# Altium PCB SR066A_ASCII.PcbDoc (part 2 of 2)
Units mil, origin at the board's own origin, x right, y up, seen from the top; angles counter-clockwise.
Board outline 2000 x 2000 mil, 4 copper layers (Top Layer, Signal Layer 1, Signal Layer 2, Bottom Layer), stack 60.434 mil thick; 64 components, 14 nets, 91 pads, 124 vias.
Unrouted connection lines stored in the file: 2.
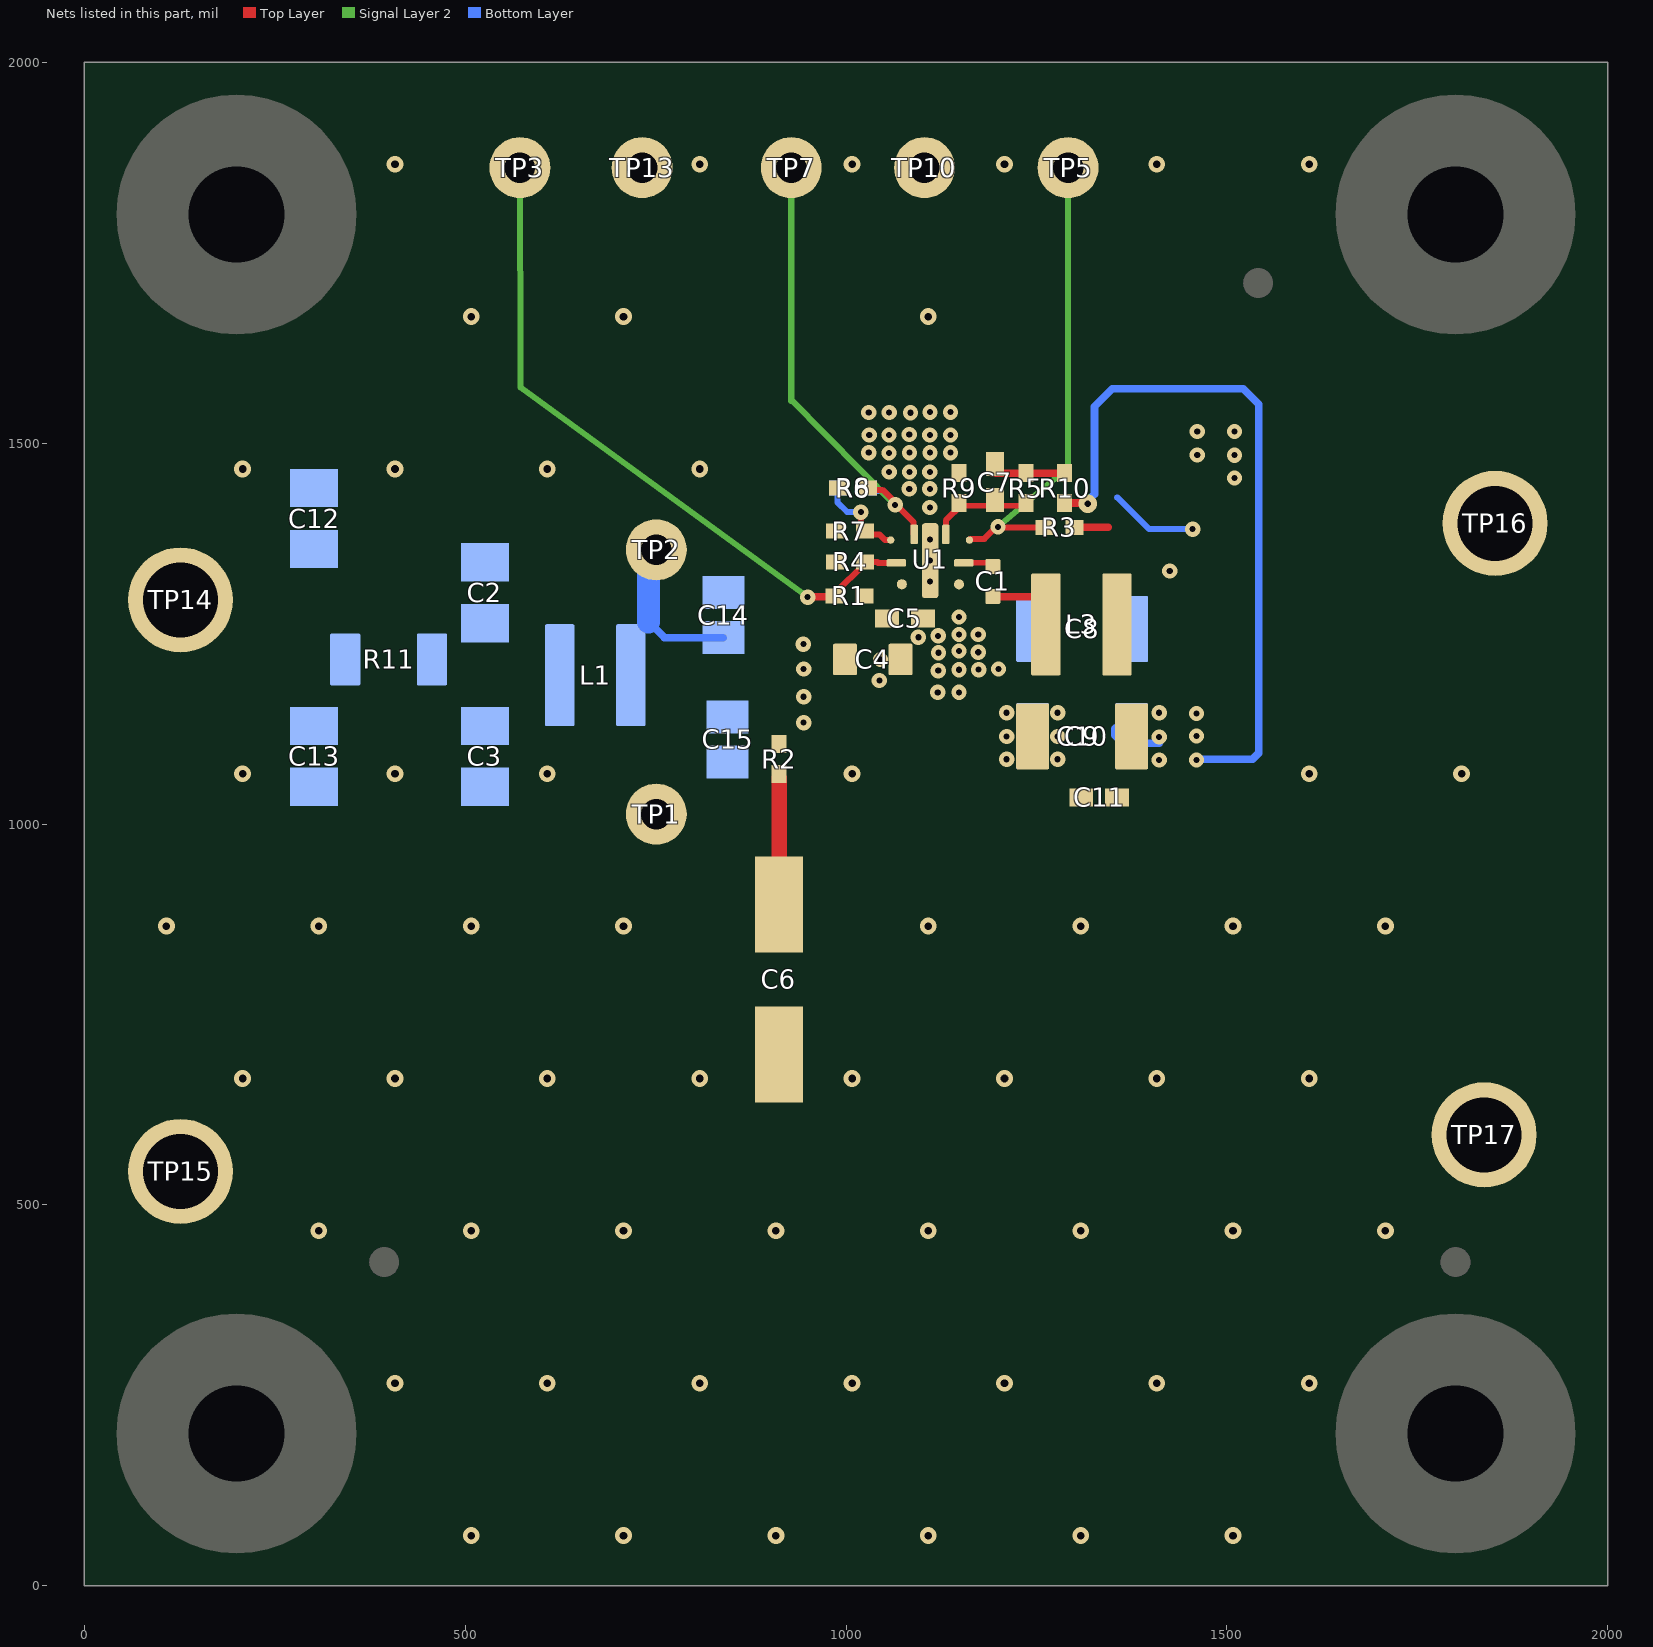
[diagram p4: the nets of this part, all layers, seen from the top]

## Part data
C1: library part CMP-0050130-1, "0.1 µF ±10% 25V Ceramic Capacitor X7R 0402 (1005 Metric)"
C2 C3 C12 C13 C14 C15: library part CMP-0007977-2, "CAP, CERM, 2.2 uF, 50 V, +/- 10%, X7R, AEC-Q200 Grade 1, 0805"
C4: library part CMP-0088943-1, "4.7µF ±10% 50V Ceramic Capacitor X7R 0805 (2012 Metric)"
C5 C11: library part CMP-0006356-2, "CAP, CERM, 0.1 uF, 50 V, +/- 10%, X7R, AEC-Q200 Grade 1, 0402"
C6: library part CMP-0011204-2, "CAP, AL, 47 uF, 50 V, +/- 20%, 0.68 ohm, AEC-Q200 Grade 2, SMD"
C7: library part CMP-0860831-1, "CAP, CERM, 22 pF, 50 V,+/- 5%, C0G/NP0, AEC-Q200 Grade 1, 0402"
C8 C9 C10: library part CMP-0043794-1, "Cap Ceramic 22uF 16V X7R 20% Pad SMD 1210 +125°C Automotive T/R"
FID1 FID2 FID3 FID4 FID5 FID6: library part CMP-0077181-1, "Fiducial mark.  There is nothing to buy or mount."
H1 H2 H3 H4: library part CMP-0003617-1, "Machine Screw, Round, #4-40 x 1/4, Nylon, Philips panhead"
H5 H6 H7 H8: library part CMP-0003610-1, "Standoff, Hex, 0.5\"L #4-40 Nylon"
L1: library part CMP-0061079-2, "Inductor, Shielded, Composite, 2.2 uH, 5.5 A, 0.0362 ohm, AEC-Q200 Grade 1, SMD"
L3: library part CMP-0120190-1, "5.6 µH Shielded Molded Inductor 5.5 A 34.7mOhm Max 1616 (4040 Metric)"
LBL1: library part CMP-0003625-1, "Thermal Transfer Printable Labels, 0.650\" W x 0.200\" H - 10,000 per roll"
Logo1: library part CMP-0074844-2
Logo2: library part CMP-0074838-1, "Texas Instrument Corporate Signature"
Logo3: library part CMP-0074847-1, "FCC_disclaimer"
Logo4: library part CMP-0074769-4
Logo5: library part CMP-0074837-2, "IEC 61010-1 Hot Surface Warning"
R1: library part CMP-0026284-2, "RES, 30.1 k, 1%, 0.063 W, AEC-Q200 Grade 0, 0402"
R2 R5 R6 R8 R10: library part CMP-0027004-2, "RES, 0, 5%, 0.063 W, 0402"
R3: library part CMP-0026823-3, "RES, 100 k, 5%, 0.063 W, AEC-Q200 Grade 0, 0402"
R4: library part CMP-0077731-1, "RES, 10.0 k, 1%, 0.063 W, AEC-Q200 Grade 0, 0402"
R7: library part CMP-0026027-3, "RES, 15.0 k, 1%, 0.063 W, AEC-Q200 Grade 0, 0402"
R9: library part CMP-0077124-1, "RES, 10.0 k, 0.1%, 0.1 W, AEC-Q200 Grade 0, 0402"
R11: library part CMP-0122408-1, "0 Ohms Jumper 0.5W, 1/2W Chip Resistor 1206 (3216 Metric) - Metal Element"
TP1 TP10 TP13: library part CMP-0055138-2, "Test Point, Miniature, Black, TH"
TP2 TP3: library part CMP-0055137-2, "Test Point, Miniature, Red, TH"
TP5: library part CMP-0055139-2, "Test Point, Miniature, White, TH"
TP7: library part CMP-0055141-2, "Test Point, Miniature, Yellow, TH"
TP14 TP15 TP16 TP17: library part CMP-0055113-1, "Terminal, Turret, TH, Double"
U1: library part CMP-0123705-1
ZZ1: library part CMP-0003616-3
ZZ2: library part CMP-0077236-1
ZZ3: library part CMP-0077237-1
ZZ4: library part CMP-0077238-1

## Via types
v1: diameter 20, hole 8, Top Layer to Bottom Layer, tented both sides, 64 vias
v2: diameter 22, hole 10, Top Layer to Bottom Layer, tented both sides, 56 vias
v3: diameter 19.68, hole 7.87, Top Layer to Bottom Layer, tented both sides, 3 vias
v4: diameter 24, hole 8, Top Layer to Bottom Layer, tented both sides, 1 vias

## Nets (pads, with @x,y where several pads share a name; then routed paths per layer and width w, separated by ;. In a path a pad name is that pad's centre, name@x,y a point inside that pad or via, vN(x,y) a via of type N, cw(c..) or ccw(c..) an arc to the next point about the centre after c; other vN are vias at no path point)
BOOT: C1.1 U1.4 | length 32.4
  Top Layer w8: U1.4@1154.69,1342.66 C1.1@1185.67,1342.97 ; C1.1@1196.63,1342.66 C1.1@1197.61,1341.67
EN: R1.1 R4.2 TP3.1 U1.9 | length 911.4
  Top Layer w8: R1.1@984.77,1299.29 986.74,1299.29 992.58,1305.13 992.58,1309.79 1017.42,1334.63 1017.42,1338.05 1023.26,1343.89 R4.2@1025.23,1343.89 1040.98,1343.89 1042.21,1342.66 U1.9@1066.11,1342.66
  Top Layer w10: v1(949.69,1297.7) 950.48,1298.49 983.98,1298.49 R1.1@984.77,1299.29
  Signal Layer 2 w8: TP3.1@572,1878 573,1574 ; 573,1573 v1(949.69,1297.7)
FB: C7.2 R5.1 R9.2 U1.6 | length 128.1
  Top Layer w8: U1.6@1131.07,1380.06 U1.6@1131.07,1380.06 1131.14,1398.49 R9.2@1151.15,1418.18 ; R9.2@1150.72,1417.98 R5.1@1232.3,1417.44
GND: C2.2 C3.2 C4.1 C5.2 C6.2 C8.1 C9.1 C10.1 C11.2 C12.2 C13.2 C14.2 C15.2 R4.1 R7.1 R8.1 R9.1 TP1.1 TP10.1 TP13.1 TP15.1 TP17.1 U1.2
  other v1: 1210.9,1084.95 1277.77,1084.95 1210.9,1114.83 1277.77,1114.95 1210.9,1145.95 1277.77,1145.95 1120.45,1172.84 1148.42,1172.84 1043.78,1188.25 1121.13,1201.21 1148.42,1202.47 1174.16,1202.61 1200.03,1203.5 1045.37,1215.97 1121.53,1224.74 1173.56,1225.42 1148.42,1227.05 1094.94,1245.07 1121,1247 1148.42,1248.79 1173.56,1248.79 1148.42,1271.54 1110.07,1415.44 1083.05,1439.87 1110.07,1439.87 1056.69,1462.14 1083.45,1462.1 1110.07,1462.1 1029.91,1487.35 1056.34,1486.97 1083.29,1487.35 1110.4,1487.35 1137,1487.35 1030.47,1510.6 1056.51,1510.6 1083.05,1511.1 1110.07,1510.6 1137,1510.6 1029.91,1540 1056.69,1540 1084.65,1539.71 1110.39,1540.49 1137,1540.49
  other v2: 508,66 708,66 908,66 1108,66 1308,66 1508,66 408,266 608,266 808,266 1008,266 1208,266 1408,266 1608,266 308,466 508,466 708,466 908,466 1108,466 1308,466 1508,466 1708,466 208,666 408,666 608,666 808,666 1008,666 1208,666 1408,666 1608,666 108,866 308,866 508,866 708,866 1108,866 1308,866 1508,866 1708,866 208,1066 408,1066 608,1066 1008,1066 1608,1066 1808,1066 208,1466 408,1466 608,1466 808,1466 508,1666 708,1666 1108,1666 408,1866 808,1866 1008,1866 1208,1866 1408,1866 1608,1866
  other v3: 1110.4,1318.05 1110.4,1345.61 1110.4,1373.17
MODE/SYNC: R6.2 R8.2 TP7.1 U1.7 | length 661.6
  Top Layer w8: R8.2@1028.95,1441.12 1031.52,1438.55 1048.07,1438.55 1064.57,1422.05 v1(1064.57,1418.93) 1065.91,1418.93 1088.81,1396.03 1088.81,1380.98 U1.7@1089.73,1380.06
  Signal Layer 2 w8: 928.13,1555.17 TP7.1@928.13,1880 ; 928.13,1557 1064.14,1418.93 v1(1064.57,1418.93)
  Bottom Layer w8: R6.2@1028.95,1440.92 1032.48,1437.39 1048.04,1437.39 1064.57,1420.86 v1(1064.57,1418.93)
NetC2_1: C2.1 C3.1 L1.1 R11.2
NetC6_1: C6.1 R2.1 | length 158.2
  Top Layer w20: R2.1@912.28,1060.32 912.44,1060.16 912.44,902.36 C6.1@912.57,902.23
NetC7_1: C7.1 R5.2 R10.1 | length 95
  Top Layer w10: C7.1@1191.91,1460.61 R5.2@1236,1460.61 R10.1@1286.9,1460.61
NetC12_1: C12.1 C13.1 R11.1 TP14.1
PGOOD: R3.2 TP5.1 U1.5 | length 613.7
  Top Layer w8: U1.5@1162.07,1372.68 1163.72,1374.33 1181.61,1374.33 1197.28,1390 v1(1199.44,1390) ; v1@1200.03,1389.41 R3.2@1259.94,1389.41
  Signal Layer 2 w8: v1@1199.45,1390.01 1291.44,1468.04 TP5.1@1291.44,1855.83
  Bottom Layer w8: v1(1199.44,1390) v1@1200.03,1389.41
RT: R6.1 R7.2 U1.8 | length 113.1
  Top Layer w8: v1@1019.46,1405.29 1019.46,1379.57 R7.2@1019.84,1379.19 ; R7.2@1029.91,1380.37 1030.47,1379.8 1044.06,1379.8 1051.02,1372.84 1058.57,1372.84 U1.8@1058.73,1372.68
  Bottom Layer w8: R6.1@989.58,1440.92 988.64,1439.99 988.64,1422.25 1001.32,1409.58 v1@1019.17,1409.58
  other v1: 1019.46,1409.29
SW: C1.2 L3.1 U1.3 | length 87.2
  Top Layer w10: C1.2@1192.85,1298.37 1253.55,1298.37 1267.84,1284.08 L3.1@1267.84,1277.76
VIN: C4.2 C5.1 C14.1 C15.1 L1.2 R1.2 R2.2 TP2.1 U1.1 | length 195.3
  Bottom Layer w10: 741,1265.3 761.83,1244.47 C14.1@839,1244.47
  Bottom Layer w30: 741,1265.3 TP2.1@741,1354
  other v1: 944.44,1133 944.44,1167 944.44,1203.5 944,1236
VOUT: C8.2 C9.2 C10.2 C11.1 L3.2 R3.1 R10.2 TP16.1 | length 1179.2
  Top Layer w10: R10.2@1286.9,1421.24 1317.29,1421.24 v4(1317.29,1420.34) ; R3.1@1299.68,1389.41 1344.05,1389.41
  Bottom Layer w8: 1356.02,1428.68 1397.76,1386.95 v1(1455,1386.95)
  Bottom Layer w10: v4(1317.29,1420.34) 1317.29,1424.13 1326.12,1432.96 1326.12,1547.71 1349.53,1571.12 1521.56,1571.12 1541.69,1551 1541.69,1093.18 1533.55,1085.04 1461.04,1085.04 v1(1460,1084) ; C10.2@1358.44,1130.53 1352.59,1124.67 1352.59,1116.39 1363.02,1105.95 v1@1411,1105.95
  other v1: 1411,1084.15 1411,1114.15 1460,1115.41 1460,1145 1411,1145.95 1424.86,1332.03 1510,1454.07 1461,1484.22 1510,1484.07 1461,1515.22 1510,1515.07
pads on no net: FID1.1 FID2.1 FID3.1 FID4.1 FID5.1 FID6.1 H1.1 H2.1 H3.1 H4.1 H5.0 H6.0 H7.0 H8.0 LBL1.0

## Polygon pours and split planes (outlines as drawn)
VIN on Top Layer "TOP_LAYER_VIN_P214" (solid, remove dead copper, pour order 214): 1081.39,1322.37 1081.39,1298.28 1069.06,1285.96 1069.06,1246.06 1040.75,1246.06 1019.46,1224.76 1019.46,1184.1 986.6,1151.25 986.6,1090.06 901.19,1090.06 901.19,1222.11 1001.46,1322.37
VOUT on Top Layer "TOP_LAYER_VOUT_P225" (solid, remove dead copper, pour order 225): 1368.86,1000.5 1458.89,1000.5 ccw(c1458.89,1038.18) 1496.57,1038.18 1496.57,1106.4 cw(c1552.17,1106.4) 1552.17,1162 1913.7,1162 ccw(c1913.7,1191.3) 1943,1191.3 1943,1521.39 ccw(c1914.4,1521.4) 1914.4,1550 1371.71,1550 ccw(c1371.71,1516.29) 1338,1516.29 1338,1031.36 ccw(c1368.86,1031.36)
GND on Top Layer "TOP_LAYER_GND_P230" (solid, remove dead copper, pour order 230): 0,2001 2,1999 2,2 2000,2 2002,4 1997,9 1997,2003
SW on Top Layer "TOP_LAYER_SW_P213" (solid, remove dead copper, pour order 213): 1138.54,1321.69 1138.85,1322 1166.75,1322 1170.42,1318.33 1215.05,1318.89 1227.23,1331.06 1292.34,1331.06 1292.34,1318.33 1292.34,1213.8 1292.34,1193.13 1235.81,1193.13 1235.81,1213.8 1159.4,1290.21 1143.55,1290.21 1138.22,1295.61
GND on Bottom Layer "BOTTOM_LAYER_GND_P233" (solid, remove dead copper, pour order 233): 4,1999 4,-2 10,4 2000,4 2000,2006 2000,1997
NetC12_1 on Bottom Layer "BOTTOM_LAYER_NETC12_1_P220" (solid, remove dead copper, pour order 220): 23.57,1100.43 23.57,1390 372.18,1390 cw(c372.18,1368.26) 393.92,1368.26 393.92,1123.39 cw(c370.95,1123.39) 370.95,1100.43
VOUT on Bottom Layer "BOTTOM_LAYER_VOUT_P221" (solid, remove dead copper, pour order 221): 1376.68,1000.5 1493.02,1000.5 ccw(c1493.02,1031.48) 1524,1031.48 1524,1535.74 ccw(c1503.74,1535.74) 1503.74,1556 1365.6,1556 ccw(c1365.6,1537.07) 1346.67,1537.11 1345.59,1031.65 ccw(c1376.68,1031.59)
VIN on Bottom Layer "BOTTOM_LAYER_VIN_P222" (solid, remove dead copper, pour order 222): 735,1119 690.44,1119 cw(c690.44,1138.44) 671,1138.44 671,1252.97 cw(c689.57,1252.97) 689.57,1271.54 943.45,1271.54 cw(c943.45,1254) 961,1253.99 961,1135.34 cw(c944.66,1135.34) 944.66,1119
NetC2_1 on Bottom Layer "BOTTOM_LAYER_NETC2_1_P224" (solid, remove dead copper, pour order 224): 431.88,1100.43 625.27,1100.43 ccw(c625.27,1123.69) 648.53,1123.69 648.53,1279.08 ccw(c633.49,1279.08) 633.49,1294.12 428.56,1294.12 ccw(c428.56,1281.32) 415.75,1281.33 415.58,1116.74 ccw(c431.88,1116.72)
GND on Signal Layer 2 "SIGNAL_LAYER_2_GND_P232" (solid, remove dead copper, pour order 232): 0,2003 4,1999 4,-2 2006,-2 2000,4 2000,1997
VOUT on Signal Layer 2 "SIGNAL_LAYER_2_VOUT_P218" (solid, remove dead copper, pour order 218): 1335.5,1021.18 1335.5,1525.92 cw(c1361.58,1525.92) 1361.58,1552 1460.5,1552 1458.5,1550 1913.84,1550 cw(c1913.84,1520.46) 1943.39,1520.45 1943.39,1199.79 cw(c1905.49,1199.78) 1905.49,1161.89 1569.07,1161.89 ccw(c1569.06,1091.82) 1499,1091.82 1499,1024.89 cw(c1470.23,1024.89) 1469.91,996.12 1359.1,997.32 cw(c1359.36,1021.18)
GND on Signal Layer 1 "SIGNAL_LAYER_1_GND_P231" (solid, remove dead copper, pour order 231): 0,2001 0,2 2,0 4,2 2002,2 2002,1988 1995,1995

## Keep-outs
Keep-Out Layer:
  the board outline again, w10
  text ".Layer_Name" at 577,-858.49 h60

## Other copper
Top Layer:
  text ".Layer_Name" at 577,-858.49 h60
Signal Layer 1:
  text ".Layer_Name" at 581,-861 h60
Signal Layer 2:
  text ".Layer_Name" at 581,-860 h60
Bottom Layer:
  text ".Layer_Name" at 577,-858.49 h60

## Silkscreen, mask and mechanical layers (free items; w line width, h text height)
Top Overlay:
  lines w3.94: 963.54,1011.75 1403.85,1011.75 1403.85,1497.83 963.54,1497.83 963.54,1011.75
  text "GND" at 673.96,1761 h35
  text "EN" at 519.44,1759 h35
  text "MODE" at 845,1759 h35
  text "GND" at 1054.07,1759 h35
  text "PGOOD" at 1207,1759 h35
  text "SYNC" at 845,1701 h35
  text "CAUTION:" at 410,1259.13 h30
  text "VOUT+" at 1755.57,1235.41 h40
  text "HOT SURFACE" at 410,1199 h30
  text "VIN_EMI+" at 44.21,1133 h40
  text "11.2mm x 12.3mm" at 968.44,962 h30
  text "GND" at 695,901 h35
  text "VOUT-" at 1756,707 h40
  text "VIN_EMI-" at 45,662 h40
  text "'.PRJ_Number'.PCB_Rev" at 731.96,286.88 h100
  text "LMR60410QEVM" at 629.63,134.15 h80
  text ".Layer_Name" at 577,-858.49 h60
Bottom Overlay:
  text ".Layer_Name" at 577,-858.49 h60
Top Paste:
  text ".Layer_Name" at 577,-858.49 h60
Bottom Paste:
  text ".Layer_Name" at 577,-858.49 h60
Top Solder:
  text ".Layer_Name" at 577,-858.49 h60
  text ".Layer_Name" at 577,-858.49 h60
Bottom Solder:
  text ".Layer_Name" at 577,-858.49 h60
Drill Guide:
  text ".Layer_Name" at 577,-858.49 h60
M1 Board Outline:
  the board outline again, w10
  text ".Layer_Name" at 577,-858.49 h60
M2 Board Dimensions:
  rectangle: 125,-400 500,-275
  rectangle: 0,-275 125,-150
  lines w7: 0,-275 1000,-275 ; 125,-400 125,-150 ; 250,-400 250,-150 ; 500,-400 500,-150 ; 750,-400 750,-150 ; 0,-400 0,-150 1000,-150 1000,-400 0,-400
  text ".Layer_Name" at 577,-858.49 h60
M3 3D STEP Top:
  text ".Layer_Name" at 577,-858.49 h60
M4 3D STEP Bottom:
  text ".Layer_Name" at 577,-858.49 h60
M5 Assembly Top:
  lines w10: -292,-930.17 6308,-930.17 ; -292,-726.83 6310,-726.83 ; -292,-523.5 -292,-1133.5 3713,-1133.5 6310,-1133.5 6310,-523.5 -291.5,-523.5 -291.5,-1133.5 1284,-1133.5 ; 2173,-1133.5 2173,-523.5 ; 3440,-726.83 3440,-523.5 ; 4280,-726.83 4280,-523.5 ; 4902,-1140 4902,-937.17
  text "COMPONENTS MARKED 'DNP' SHOULD NOT BE POPULATED." at 1153.5,-318.5 h60
  text "ASSEMBLY VARIANT:" at 1153,-434 h60
  text ".VariantName" at 2189,-434 h60
  text "PCB VIEWED FROM TOP SIDE" at -228.5,-655.67 h60
  text "BOARD #:" at 2248,-655.67 h60
  text ".PRJ_Number" at 2793.5,-655.67 h60
  text "REV:" at 3638,-655.67 h60
  text ".PCB_Rev" at 3929.5,-655.67 h60
  text "SVN REV:" at 4476,-655.67 h60
  text ".VersionControl_RevNumber" at 4982,-655.67 h60
  text "TID #:" at 2248,-859 h60
  text ".TID" at 2793.5,-859 h60
  text "PLOT NAME =" at -228.5,-1064.34 h60
  text ".plot_File_Name" at 577,-1064.34 h60
  text "GENERATED    :" at 2250,-1064.34 h60
  text ".Print_Date" at 3119.5,-1064.34 h60
  text ".Print_Time" at 3848.5,-1064.34 h60
  text "TEXAS INSTRUMENTS" at 5113,-1064.34 h60
M6 Assembly Bottom:
  lines w10: -292.5,-727.33 6309.5,-727.33 ; -290.5,-930.67 6309.5,-930.67 ; 1115.5,-1140.5 1115.5,-937.67 ; 1737.5,-727.33 1737.5,-524 ; 2577.5,-727.33 2577.5,-524 ; 3844.5,-1134 3844.5,-524 ; 4733.5,-1134 6309,-1134 6309,-524 -292.5,-524 -292.5,-1134 2304.5,-1134 6309.5,-1134 6309.5,-524
  text "COMPONENTS MARKED 'DNP' SHOULD NOT BE POPULATED." at 6102,-318 h60
  text ".VariantName" at 5058,-434 h60
  text "ASSEMBLY VARIANT:" at 6097,-434 h60
  text ".VersionControl_RevNumber" at 1035.5,-656.17 h60
  text "SVN REV:" at 1541.5,-656.17 h60
  text ".PCB_Rev" at 2088,-656.17 h60
  text "REV:" at 2379.5,-656.17 h60
  text ".PRJ_Number" at 3224,-656.17 h60
  text "BOARD #:" at 3769.5,-656.17 h60
  text "PCB VIEWED FROM BOTTOM SIDE" at 6246,-656.17 h60
  text ".TID" at 3224,-859.5 h60
  text "TID #:" at 3769.5,-859.5 h60
  text "TEXAS INSTRUMENTS" at 904.5,-1064.84 h60
  text ".Print_Time" at 2169,-1064.84 h60
  text ".Print_Date" at 2898,-1064.84 h60
  text "GENERATED    :" at 3767.5,-1064.84 h60
  text ".plot_File_Name" at 5440.5,-1064.84 h60
  text "PLOT NAME =" at 6246,-1064.84 h60
M9 Title Sheet:
  lines w10: -491.5,1041.5 -291.5,1041.5 ; -491.5,3416.5 -291.5,3416.5 ; -491.5,5791.5 -291.5,5791.5 ; 2008.5,-1333.5 2008.5,-1133.5 ; 2008.5,7966.5 2008.5,8166.5 ; 4508.5,-1333.5 4508.5,-1133.5 ; 4508.5,7966.5 4508.5,8166.5 ; 6321,-1133.5 6321,-523.5 11303.5,-523.5 ; 7008.5,-1333.5 7008.5,-1133.5 ; 7008.5,7966.5 7008.5,8166.5 ; 9508.5,-1333.5 9508.5,-1133.5 ; 9508.5,7966.5 9508.5,8166.5 ; 11303.5,-1133.5 11303.5,-523.5 ; 11303.5,-823.5 14303.5,-823.5 ; 11303.5,-223.5 14303.5,-223.5 ; 11304.5,370.5 14304.5,370.5 ; 12008.5,-1333.5 12008.5,-1133.5 ; 12008.5,7966.5 12008.5,8166.5 ; 12808.5,-1123.5 12808.5,-523.5 ; 14303.5,-523.5 11303.5,-523.5 ; 14303.5,76.5 11303.5,76.5 ; 14308.5,66.5 14308.5,-1133.5 ; 14308.5,871 11304.5,871 11303.5,871 11303.5,370.5 11303.5,76.5 ; 14308.5,1041.5 14508.5,1041.5 ; 14308.5,3416.5 14508.5,3416.5 ; 14308.5,5791.5 14508.5,5791.5 ; 11303.5,-523.5 11303.5,76.5 ; 14308.5,-1133.5 -291.5,-1133.5 -291.5,7966.5 14308.5,7966.5 14308.5,-1133.5 ; -491.5,-1333.5 14508.5,-1333.5 14508.5,8166.5 -491.5,8166.5 -491.5,-1333.5
  text "1" at 739.84,8036.5 h70
  text "2" at 3235.5,8036.5 h70
  text "3" at 5724.84,8036.5 h70
  text "4" at 8231.51,8036.5 h70
  text "5" at 10730.5,8036.5 h70
  text "6" at 13235.5,8036.5 h70
  text "A" at -416.5,6893.5 h70
  text "A" at 14383.5,6893.5 h70
  text "B" at -416.5,4513.5 h70
  text "B" at 14383.5,4513.5 h70
  text "C" at -416.5,2138.5 h70
  text "C" at 14383.5,2138.5 h70
  text "PROJECT TITLE:" at 11343.5,277.5 h45
  text ".PRJ_Title" at 11393.5,144.17 h70
  text "DESIGNED FOR:" at 11343.5,-23.5 h45
  text ".PRJ_Customer" at 11393.5,-163.5 h70
  text "D" at -416.5,-231.5 h70
  text "D" at 14383.5,-231.5 h70
  text "FILE NAME:" at 11343.5,-323.5 h45
  text ".PCB_File_Name_No_Path" at 11393.5,-443.5 h70
  text "Texas Instruments (TI) and/or its licensors do not warrant the accuracy or completeness of this specification" at 6374,-605.34 h45
  text "ENGINEER:" at 11343.5,-613.5 h45
  text "LAYOUT BY:" at 12848.5,-613.5 h45
  text "or any information contained therein. TI and/or its licensors do not warrant that this design will meet" at 6329.01,-718 h45
  text ".PRJ_Engineer" at 11393.5,-768.49 h70
  text ".PCB_Layout" at 12899,-768.49 h70
  text "the specifications, will be suitable for your application or fit for any particular purpose, or will operate in" at 6329.01,-830.67 h45
  text ".Layer_Name" at 577,-858.49 h60
  text "ALTIUM DESIGNER VERSION:" at 12848.5,-923.5 h45
  text "an implementation. TI and/or its licensors do not warrant that the design is production worthy. You should" at 6329.01,-943.33 h45
  text "completely validate and test your design implementation to confirm the system functionality for your application." at 6374,-1056 h45
  text ".print_Scale" at 11393.5,-1056.83 h70
  text ".Application_BuildNumber" at 12899,-1056.83 h70
  text "1" at 739.84,-1263.5 h70
  text "2" at 3235.5,-1263.5 h70
  text "3" at 5724.84,-1263.5 h70
  text "4" at 8231.51,-1263.5 h70
  text "5" at 10730.5,-1263.5 h70
  text "6" at 13235.5,-1263.5 h70
M10 Fab Notes:
  drawing of 189 lines, arcs and shapes, not listed
  text "DESIGN INFORMATION" at 12382.02,6356.17 h60
  text "MIN. TRACK WIDTH:" at 11737.46,6224.05 h60
  text "8" at 12833.7,6224.05 h60
  text "MIL" at 12988.46,6224.05 h60
  text "MIN. CLEARANCE:" at 11737.46,6099.92 h60
  text "0.2" at 12773.7,6099.93 h60
  text "mm" at 12988.46,6099.92 h60
  text "MIN. VIA PAD SIZE:" at 11737.46,5975.8 h60
  text "24" at 12803.71,5975.8 h60
  text "MIL" at 12988.46,5975.8 h60
  text "0.05mm (2MIL)" at 12432.46,5845.9 h60
  text "MINIMUM ANNULAR RING" at 11408.23,5837.67 h60
  text "EXTERNAL" at 13140.46,5837.67 h60
  text "PER" at 11608.23,5727.55 h60
  text "IPC-D-275 CLASS 2 LEVEL C" at 11828.23,5727.54 h60
  text "MIL, HOLES" at 13316.46,5627.07 h60
  text "+/-" at 12924,5618.48 h60
  text "+/-" at 13778,5618.48 h60
  text "REGISTRATION TOLERANCES:" at 11408.23,5617.42 h60
  text "METAL" at 12608,5617.42 h60
  text "5" at 13184.2,5617.42 h60
  text "3" at 14017.2,5617.42 h60
  text "MIL" at 14133.46,5617.42 h60
  text "HOLE SIZE TOLERANCE (UNLESS OTHERWISE SPECIFIED):" at 11408.23,5519.1 h60
  text "+/-" at 13778,5516.23 h60
  text "3" at 14017.2,5515.17 h60
  text "MIL" at 14133.46,5515.17 h60
  text "MATERIAL:" at 11333.46,5377.52 h60
  text "FR-4 High Tg" at 12319.9,5249 h60
  text "X" at 12175.46,5241.01 h60
  text "FR-408" at 11754.46,5236.49 h60
  text "OTHER" at 13242.46,5236.49 h60
  text "62 MIL (1.6mm) +/-10%" at 12074.56,5093.46 h60
  text "X" at 11954.46,5091.01 h60
  text "THICKNESS:" at 11408.23,5085.24 h60
  text "OTHER" at 13359.46,5085.24 h60
  text "TOLERANCE:" at 11408.23,4946.92 h60
  text "X" at 12256.46,4946.92 h60
  text "ANSI IPC-6012 TYPE 3 CLASS 2" at 12434.48,4946.92 h60
  text "OTHER +/-" at 12434.46,4802.73 h60
  text "BOW & TWIST:" at 11408.23,4657.54 h60
  text "X" at 12256.46,4657.54 h60
  text "ANSI IPC-6012 TYPE 3 CLASS 2" at 12434.48,4657.54 h60
  text "OTHER +/-" at 12434.46,4510.85 h60
  text "DRILLING:" at 11333.46,4380.23 h60
  text "NC_DRILL FILES" at 13094.46,4275.04 h60
  text "REFERENCE:" at 11408.23,4271.1 h60
  text "X" at 12065.46,4271.01 h60
  text "AS SHOWN" at 12243.46,4271.1 h60
  text "X" at 12966.46,4271.1 h60
  text "OTHER" at 13392.46,4128.85 h60
  text "PTH COPPER THICKNESS:" at 11407.91,4125.32 h60
  text "X" at 12547.14,4125.32 h60
  text "20-30 um" at 12675.14,4125.32 h60
  text "BOARD FINISH:" at 11333.46,3977.73 h60
  text "SILKSCREEN:" at 11488.68,3867.6 h60
  text "X" at 12446.46,3867.6 h60
  text "TOP" at 12563.46,3867.6 h60
  text "X" at 12956.46,3867.6 h60
  text "BOTTOM" at 13074.46,3867.6 h60
  text "SILKSCREEN COLOR:" at 11488.68,3712.41 h60
  text "X" at 12445.46,3712.41 h60
  text "WHITE" at 12563.46,3712.41 h60
  text "OTHER" at 13074.46,3712.41 h60
  text "X" at 12576.46,3568.96 h60
  text "GREEN" at 12694.46,3568.96 h60
  text "OTHER" at 13312.46,3568.96 h60
  text "SOLDER RESIST COLOR:" at 11488.68,3562.1 h60
  text "X" at 12576.46,3414.71 h60
  text "MATTE" at 12694.46,3414.71 h60
  text "SEMI-GLOSS" at 13312,3414.07 h60
  text "IMMERSION GOLD (ENIG)" at 12394.46,3241.94 h60
  text "ENEPIG" at 13732,3234.72 h60
  text "SURFACE FINISH:" at 11333.46,3233.72 h60
  text "X" at 12216.46,3233.72 h60
  text "IMM. TIN/SILVER OR EQUIV" at 11663,3096.4 h60
  text "OTHER" at 13094.46,3092.47 h60
  text "ARRAY/PANEL:" at 11333.46,2937.09 h60
  text "CUT AND TRIM PER M1 BOARD OUTLINE" at 12394.46,2928.87 h60
  text "N.C. ROUTE" at 12394.46,2792.9 h60
  text "X" at 13082.46,2792.9 h60
  text "V. SCORE" at 13260.46,2792.9 h60
  text "CERTIFICATION:" at 11333.46,2663.77 h60
  text "MATERIALS AND WORKMANSHIP FOR ALL PCBS" at 12058.46,2663.77 h60
  text "TO MEET OR EXCEED THE REQUIREMENTS OF:" at 12058.46,2569.71 h60
  text "X" at 11695.97,2441.08 h60
  text "ANSI IPC-A-600F CLASS ->" at 11823.96,2441.08 h60
  text "X" at 13471.97,2441.08 h60
  text "2" at 13581.96,2441.08 h60
  text "1" at 13266.96,2439.58 h60
  text "3" at 13935.96,2439.58 h60
  text "X" at 12507.97,2293.39 h60
  text "RoHS" at 12635.96,2293.39 h60
  text "OTHER" at 13280.36,2293.39 h60
  text "PER ORDER" at 13677.42,2293.39 h60
  text "ALL BOARDS MUST MEET OR EXCEED UL94-V0 REQUIREMENTS." at 11361,2139.57 h60
  text "PCB MUST BEAR THE UL94V-0 UL REGISTERED MATERIAL ID NUMBER" at 11361,2023.5 h60
  text "ADDITIONAL REQUIREMENTS:" at 11333.46,1854.08 h60
  text "MICROSECTION:" at 11408.23,1746.95 h60
  text "YES" at 12313.96,1746.95 h60
  text "REQUIRED" at 13175.46,1602.62 h60
  text "BARE BOARD ELEC. TEST:" at 11408.23,1599.76 h60
  text "NONE" at 12713.96,1599.76 h60
  text "X" at 13057.46,1599.76 h60
  text "PER ORDER" at 13767.46,1599.76 h60
  text "XX MIL VIAS REQUIRE NON-CONDUCTIVE FILL AND PLANARIZE" at 11576.38,1394.82 h59
  text "XX MIL VIAS REQUIRE CONDUCTIVE FILL AND PLANARIZE" at 11584.38,1290.84 h60
  text "OUTER XX MIL TRACES REQUIRE 50 OHM SINGLE-ENDED IMPEDANCE" at 11583.39,1127.46 h58
  text "LAYER 2 & 3 (INNER LAYERS) XX MIL WIDE, XX MIL SPACE / TRACES REQUIRE 100 OHM DIFFERENTIAL IMPEDANCE" at 11575.39,891.74 h60
  text ".Layer_Name" at 577,-858.49 h60
M11 Gerber Information:
  lines w10: -292,-930.17 6308,-930.17 ; -292,-726.83 6310,-726.83 ; -292,-523.5 -292,-1133.5 3713,-1133.5 6310,-1133.5 6310,-523.5 -291.5,-523.5 -291.5,-1133.5 1284,-1133.5 ; 2173,-1133.5 2173,-523.5 ; 3440,-726.83 3440,-523.5 ; 4280,-726.83 4280,-523.5 ; 4902,-1140 4902,-937.17
  text "ALL ARTWORK VIEWED FROM TOP SIDE" at -228.5,-655.67 h60
  text "BOARD #:" at 2248,-655.67 h60
  text ".PRJ_Number" at 2793.5,-655.67 h60
  text "REV:" at 3638,-655.67 h60
  text ".PCB_Rev" at 3929.5,-655.67 h60
  text "SVN REV:" at 4476,-655.67 h60
  text ".VersionControl_RevNumber" at 4982,-655.67 h60
  text "LAYER NAME =" at -228.5,-858.49 h60
  text "TID #:" at 2248,-859 h60
  text ".TID" at 2793.5,-859 h60
  text "PLOT NAME =" at -228.5,-1064.34 h60
  text ".plot_File_Name" at 577,-1064.34 h60
  text "GENERATED    :" at 2250,-1064.34 h60
  text ".Print_Date" at 3119.5,-1064.34 h60
  text ".Print_Time" at 3848.5,-1064.34 h60
  text "TEXAS INSTRUMENTS" at 5113,-1064.34 h60
M12 Stackup:
  drawing of 295 lines, arcs and shapes, not listed
  text "Layer" at 9820.35,7845 h60
  text "Name" at 10230.26,7845 h60
  text "Material" at 11170,7845 h60
  text "Thickness" at 12029.77,7845 h60
  text "Constant" at 12679.6,7845 h60
  text "Board Layer Stack" at 13249.46,7845 h60
  text "Top Overlay" at 10230.26,7725 h60
  text "Top Solder" at 10230.26,7605 h60
  text "Solder Resist" at 11170,7605 h60
  text "0.40mil" at 12029.77,7605 h60
  text "3.5" at 12679.6,7605 h60
  text "1" at 9820.35,7485 h60
  text "Top Layer" at 10230.26,7485 h60
  text "2.80mil" at 12029.77,7485 h60
  text "Dielectric 1" at 10230.26,7365 h60
  text "FR-4 High Tg" at 11170,7365 h60
  text "10.00mil" at 12029.77,7365 h60
  text "4.2" at 12679.6,7365 h60
  text "2" at 9820.35,7245 h60
  text "Signal Layer 1" at 10230.26,7245 h60
  text "1.42mil" at 12029.77,7245 h60
  text "Dielectric2" at 10230.26,7125 h60
  text "FR-4 High Tg" at 11170,7125 h60
  text "32.00mil" at 12029.77,7125 h60
  text "4.2" at 12679.6,7125 h60
  text "3" at 9820.35,7005 h60
  text "Signal Layer 2" at 10230.26,7005 h60
  text "1.42mil" at 12029.77,7005 h60
  text "Dielectric 3" at 10230.26,6885 h60
  text "FR-4 High Tg" at 11170,6885 h60
  text "10.00mil" at 12029.77,6885 h60
  text "4.2" at 12679.6,6885 h60
  text "4" at 9820.35,6765 h60
  text "Bottom Layer" at 10230.26,6765 h60
  text "2.80mil" at 12029.77,6765 h60
  text "Bottom Solder" at 10230.26,6645 h60
  text "Solder Resist" at 11170,6645 h60
  text "0.40mil" at 12029.77,6645 h60
  text "3.5" at 12679.6,6645 h60
  text "Bottom Overlay" at 10230.26,6525 h60
  text "Total board thickness:" at 9820.35,6405 h60
  text "61.23mil" at 12029.77,6405 h60
  text ".Layer_Name" at 577,-858.49 h60
M13 Component Bodies Top:
  text ".Layer_Name" at 577,-858.49 h60
M14 Component Bodies Bottom:
  text ".Layer_Name" at 577,-858.49 h60
M15 Courtyards Top:
  text ".Layer_Name" at 577,-858.49 h60
M16 Courtyards Bottom:
  text ".Layer_Name" at 577,-858.49 h60
Drill Drawing:
  circle w10: c5863.72,2949 r27.63
  lines w10: 5836.09,2797.06 5891.34,2797.06 5891.34,2852.31 5836.09,2852.31 5836.09,2797.06 ; 5836.09,3045.7 5863.72,3059.51 5891.34,3045.7 5877.53,3073.32 5891.34,3100.95 5863.72,3087.14 5836.09,3100.95 5849.9,3073.32 5836.09,3045.7 ; 5836.09,3183.83 5849.9,3183.83 5849.9,3170.02 5877.53,3170.02 5877.53,3183.83 5891.34,3183.83 5891.34,3211.46 5877.53,3211.46 5877.53,3225.27 5849.9,3225.27 5849.9,3211.46 5836.09,3211.46 5836.09,3183.83 ; 5836.09,3349.59 5891.34,3349.59 5863.72,3294.34 5836.09,3349.59 ; 5836.09,3432.47 5849.9,3432.47 5863.72,3418.66 5877.53,3432.47 5891.34,3432.47 5877.53,3446.28 5891.34,3460.1 5877.53,3460.1 5863.72,3473.91 5849.9,3460.1 5836.09,3460.1 5849.9,3446.28 5836.09,3432.47
  lines w12: 5786,2759.76 9017.49,2759.76 ; 5786,3505.68 9017.49,3505.68 ; 6123.86,2635.44 6123.86,3630 ; 6455.86,2635.44 6455.86,3630 ; 7092.43,2635.44 7092.43,3630 ; 7351.57,2635.44 7351.57,3630 ; 7726.72,2635.44 7726.72,3630 ; 8451.05,2635.44 8451.05,3630 ; 5786,2635.44 9017.49,2635.44 9017.49,3630 5786,3630 5786,2635.44
  text "Symbol" at 5860.59,3542.98 h72
  text "Quantity" at 6161.16,3542.98 h72
  text "Finished Hole Size" at 6493.16,3542.98 h72
  text "Plated" at 7129.72,3542.98 h72
  text "Hole Type" at 7388.86,3542.98 h72
  text "Drill Layer Pair" at 7764.02,3542.98 h72
  text "Hole Tolerance" at 8488.35,3542.98 h72
  text "3" at 6161.16,3418.66 h60
  text "7.87mil (0.200mm)" at 6493.16,3418.66 h60
  text "PTH" at 7129.72,3418.66 h60
  text "Round" at 7388.86,3418.66 h60
  text "Top Layer - Bottom Layer" at 7764.02,3418.66 h60
  text "65" at 6161.16,3294.34 h60
  text "8.00mil (0.203mm)" at 6493.16,3294.34 h60
  text "PTH" at 7129.72,3294.34 h60
  text "Round" at 7388.86,3294.34 h60
  text "Top Layer - Bottom Layer" at 7764.02,3294.34 h60
  text "56" at 6161.16,3170.02 h60
  text "10.00mil (0.254mm)" at 6493.16,3170.02 h60
  text "PTH" at 7129.72,3170.02 h60
  text "Round" at 7388.86,3170.02 h60
  text "Top Layer - Bottom Layer" at 7764.02,3170.02 h60
  text "7" at 6161.16,3045.7 h60
  text "40.00mil (1.016mm)" at 6493.16,3045.7 h60
  text "PTH" at 7129.72,3045.7 h60
  text "Round" at 7388.86,3045.7 h60
  text "Top Layer - Bottom Layer" at 7764.02,3045.7 h60
  text "4" at 6161.16,2921.38 h60
  text "98.43mil (2.500mm)" at 6493.16,2921.38 h60
  text "PTH" at 7129.72,2921.38 h60
  text "Round" at 7388.86,2921.38 h60
  text "Top Layer - Bottom Layer" at 7764.02,2921.38 h60
  text "4" at 6161.16,2797.06 h60
  text "125.98mil (3.200mm)" at 6493.16,2797.06 h60
  text "PTH" at 7129.72,2797.06 h60
  text "Round" at 7388.86,2797.06 h60
  text "Top Layer - Bottom Layer" at 7764.02,2797.06 h60
  text "139 Total" at 6161.16,2672.74 h60
  text ".Layer_Name" at 577,-858.49 h60
M17 Embedded Cavity:
  text ".Layer_Name" at 577,-858.49 h60
M18 Embedded Assembly:
  text ".Layer_Name" at 577,-858.49 h60
M19 Embedded Keepout:
  text ".Layer_Name" at 577,-858.49 h60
